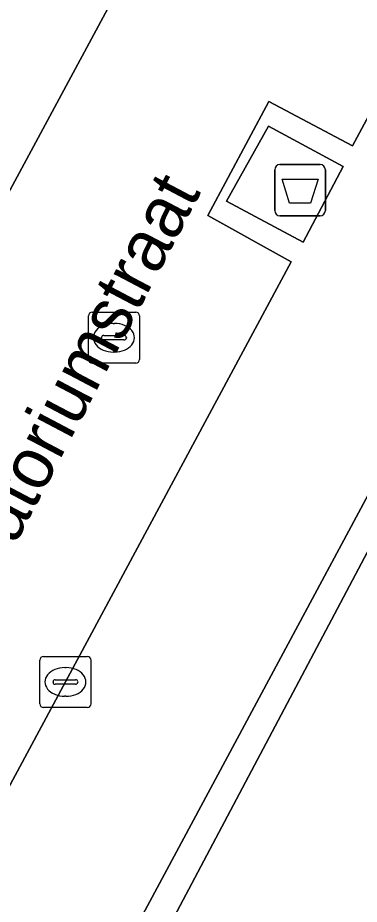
# Model space of a CAD drawing. Extents: x 159489 to 160304, y 383825 to 384531.
# Drawn here: x 159635.59 to 159642.27, y 384190.24 to 384207.56 of the extents above; entities that cross this region are included whole.
import ezdxf

# ---------------------------------------------------------------- set-up
doc = ezdxf.new("R2010")
doc.units = 0
for name, color, linetype in [('IMGEO_Afval_apart_plaats', 7, 'Continuous'), ('IMGEO_Groenvoorziening', 7, 'Continuous'), ('IMGEO_Haag', 7, 'Continuous'), ('IMGEO_Kolk', 7, 'Continuous'), ('IMGEO_Openbare_ruimte_label', 7, 'Continuous'), ('IMGEO_Parkeervlak_open', 7, 'Continuous'), ('IMGEO_Rijbaan_lokaal_gesloten', 7, 'Continuous'), ('IMGEO_Rioolput', 7, 'Continuous'), ('IMGEO_Voetpad_gesloten', 7, 'Continuous'), ('IMGEO_Voetpad_open', 7, 'Continuous')]:
    doc.layers.add(name, color=color, linetype=linetype)

msp = doc.modelspace()

# ---------------------------------------------------------------- linework, layer by layer
at = {"layer": 'IMGEO_Afval_apart_plaats'}
for p, q in [((159640.715, 384204.69), (159641.505, 384204.69)), ((159641.505, 384204.69), (159640.715, 384204.69)), ((159640.615, 384203.79), (159640.615, 384204.59)), ((159640.615, 384204.59), (159640.615, 384203.79)), ((159641.605, 384204.59), (159641.605, 384203.79)), ((159641.605, 384203.79), (159641.605, 384204.59)), ((159641.505, 384203.69), (159640.715, 384203.69)), ((159640.715, 384203.69), (159641.505, 384203.69))]:
    msp.add_line(p, q, dxfattribs=at)
msp.add_lwpolyline([(159640.758, 384204.404), (159641.462, 384204.404), (159641.313, 384203.934), (159640.907, 384203.934), (159640.758, 384204.404)], dxfattribs=at)
for centre, start, end in [((159640.715, 384204.59), 90, 180), ((159640.715, 384204.59), 90, 180), ((159641.505, 384204.59), 0, 90), ((159641.505, 384204.59), 360, 90), ((159640.715, 384203.79), 180, 270), ((159640.715, 384203.79), 180, 270), ((159641.505, 384203.79), 270, 0), ((159641.505, 384203.79), 270, 0)]:
    msp.add_arc(centre, 0.1, start, end, dxfattribs=at)
at = {"layer": 'IMGEO_Groenvoorziening'}
for points in [[(159638.312, 384209.524), (159639.366, 384211.481), (159637.113, 384212.661), (159633.141, 384205.225), (159635.354, 384204.03)], [(159637.45, 384187.678), (159638.592, 384189.885), (159647.537, 384206.76), (159652.006, 384204.401), (159652.186, 384204.749), (159647.326, 384207.335), (159624.039, 384163.992), (159628.847, 384161.508), (159629.249, 384161.301), (159629.469, 384161.725), (159624.879, 384164.058), (159626.156, 384166.276)]]:
    msp.add_lwpolyline(points, close=True, dxfattribs=at)
at = {"layer": 'IMGEO_Haag'}
msp.add_lwpolyline([(159637.45, 384187.678), (159638.592, 384189.885), (159647.537, 384206.76), (159652.006, 384204.401), (159652.186, 384204.749), (159647.326, 384207.335), (159624.039, 384163.992), (159628.847, 384161.508), (159629.249, 384161.301), (159629.469, 384161.725), (159624.879, 384164.058), (159626.156, 384166.276)], close=True, dxfattribs=at)
at = {"layer": 'IMGEO_Kolk'}
for p, q in [((159636.024, 384194.157), (159636.024, 384195.009)), ((159636.099, 384195.083), (159636.951, 384195.083)), ((159637.025, 384195.009), (159637.025, 384194.157)), ((159636.512, 384194.863), (159636.537, 384194.863)), ((159636.326, 384194.626), (159636.724, 384194.626)), ((159636.283, 384194.577), (159636.283, 384194.589)), ((159636.721, 384194.54), (159636.323, 384194.54)), ((159636.767, 384194.589), (159636.767, 384194.577)), ((159636.535, 384194.303), (159636.51, 384194.303)), ((159636.951, 384194.083), (159636.099, 384194.083))]:
    msp.add_line(p, q, dxfattribs=at)
for points in [[(159636.024, 384194.157), (159636.024, 384195.009)], [(159636.099, 384195.083), (159636.951, 384195.083)], [(159637.025, 384195.009), (159637.025, 384194.157)], [(159636.951, 384194.083), (159636.099, 384194.083)]]:
    msp.add_lwpolyline(points, dxfattribs=at)
for centre, radius, start, end in [((159636.101, 384195.007), 0.0765, 91.552, 178.448), ((159636.101, 384195.007), 0.0765, 91.552, 178.448), ((159636.949, 384195.007), 0.0765, 1.552, 88.448), ((159636.949, 384195.007), 0.0765, 1.552, 88.448), ((159636.323, 384194.586), 0.0403, 85.8775, 175.7526), ((159636.728, 384194.588), 0.0386, 1.7309, 96.639), ((159636.32, 384194.576), 0.0366, 178.938, 274.7102), ((159636.724, 384194.583), 0.043, 264.8664, 352.4533), ((159636.101, 384194.159), 0.0765, 181.552, 268.448), ((159636.101, 384194.159), 0.0765, 181.552, 268.448), ((159636.949, 384194.159), 0.0765, 271.552, 358.448), ((159636.949, 384194.159), 0.0765, 271.552, 358.448)]:
    msp.add_arc(centre, radius, start, end, dxfattribs=at)
for centre, major_axis, ratio, start_param, end_param in [((159636.511, 384194.583), (-0.387, 0.002), 0.722429, 4.712389, 7.853982), ((159636.536, 384194.583), (-0.39, 0.002), 0.717154, 1.570796, 4.712389)]:
    msp.add_ellipse(centre, major_axis=major_axis, ratio=ratio, start_param=start_param, end_param=end_param, dxfattribs=at)
at = {"layer": 'IMGEO_Parkeervlak_open'}
msp.add_lwpolyline([(159652.006, 384204.401), (159647.537, 384206.76), (159638.592, 384189.885), (159643.082, 384187.51)], close=True, dxfattribs=at)
at = {"layer": 'IMGEO_Rijbaan_lokaal_gesloten'}
for points in [[(159654.684, 384240.484), (159653.747, 384238.682), (159646.166, 384224.11), (159643.655, 384219.446), (159639.366, 384211.481), (159638.312, 384209.524), (159635.354, 384204.03), (159631.805, 384197.437), (159631.422, 384196.726), (159624.053, 384183.005), (159617.514, 384170.805), (159617.293, 384170.392), (159616.523, 384168.93), (159615.471, 384167.017)], [(159636.525, 384194.583), (159640.934, 384202.788), (159639.307, 384203.695), (159640.5, 384205.922), (159642.138, 384205.059), (159643.404, 384207.416), (159644.131, 384208.747), (159647.908, 384215.784), (159651.321, 384222.115), (159658.978, 384236.342), (159659.656, 384237.603), (159660.392, 384238.832)], [(159617.96, 384161.026), (159619.063, 384162.111), (159619.143, 384162.254), (159621.259, 384166.179), (159621.791, 384167.209), (159629.16, 384180.893), (159636.525, 384194.583)]]:
    msp.add_lwpolyline(points, dxfattribs=at)
at = {"layer": 'IMGEO_Rioolput'}
for p, q in [((159636.973, 384200.882), (159636.973, 384201.734)), ((159637.048, 384201.808), (159637.9, 384201.808)), ((159637.974, 384201.734), (159637.974, 384200.882)), ((159637.461, 384201.588), (159637.486, 384201.588)), ((159637.232, 384201.302), (159637.232, 384201.314)), ((159637.67, 384201.265), (159637.272, 384201.265)), ((159637.275, 384201.351), (159637.673, 384201.351)), ((159637.716, 384201.314), (159637.716, 384201.302)), ((159637.484, 384201.028), (159637.459, 384201.028)), ((159637.9, 384200.808), (159637.048, 384200.808))]:
    msp.add_line(p, q, dxfattribs=at)
for points in [[(159636.973, 384200.882), (159636.973, 384201.734)], [(159637.048, 384201.808), (159637.9, 384201.808)], [(159637.974, 384201.734), (159637.974, 384200.882)], [(159637.9, 384200.808), (159637.048, 384200.808)]]:
    msp.add_lwpolyline(points, dxfattribs=at)
for centre, radius, start, end in [((159637.05, 384201.732), 0.0765, 91.552, 178.448), ((159637.05, 384201.732), 0.0765, 91.552, 178.448), ((159637.898, 384201.732), 0.0765, 1.552, 88.448), ((159637.898, 384201.732), 0.0765, 1.552, 88.448), ((159637.272, 384201.311), 0.0403, 85.8775, 175.7526), ((159637.269, 384201.301), 0.0366, 178.938, 274.7102), ((159637.673, 384201.308), 0.043, 264.8664, 352.4533), ((159637.677, 384201.313), 0.0386, 1.7309, 96.639), ((159637.05, 384200.884), 0.0765, 181.552, 268.448), ((159637.05, 384200.884), 0.0765, 181.552, 268.448), ((159637.898, 384200.884), 0.0765, 271.552, 358.448), ((159637.898, 384200.884), 0.0765, 271.552, 358.448)]:
    msp.add_arc(centre, radius, start, end, dxfattribs=at)
for centre, major_axis, ratio, start_param, end_param in [((159637.46, 384201.308), (-0.387, 0.002), 0.722429, 4.712389, 7.853982), ((159637.485, 384201.308), (-0.39, 0.002), 0.717154, 1.570796, 4.712389)]:
    msp.add_ellipse(centre, major_axis=major_axis, ratio=ratio, start_param=start_param, end_param=end_param, dxfattribs=at)
at = {"layer": 'IMGEO_Voetpad_gesloten'}
msp.add_lwpolyline([(159641.952, 384204.655), (159640.492, 384205.437), (159639.672, 384203.978), (159641.17, 384203.172)], close=True, dxfattribs=at)
at = {"layer": 'IMGEO_Voetpad_open'}
for points in [[(159647.326, 384207.335), (159649.078, 384210.598), (159649.663, 384210.272), (159651.431, 384213.623), (159651.297, 384213.694), (159651.4, 384213.888), (159648.7, 384215.354), (159644.915, 384208.328), (159644.131, 384208.747), (159643.404, 384207.416), (159642.138, 384205.059), (159640.5, 384205.922), (159639.307, 384203.695), (159640.934, 384202.788), (159636.525, 384194.583), (159629.16, 384180.893), (159621.791, 384167.209), (159621.259, 384166.179), (159622.029, 384165.74), (159619.927, 384161.842), (159619.143, 384162.254), (159619.063, 384162.111), (159617.96, 384161.026)], [(159613.734, 384158.126), (159604.421, 384153.122), (159601.595, 384151.633), (159604.764, 384149.496), (159618.169, 384156.621), (159620.642, 384157.928), (159622.146, 384160.474), (159622.471, 384161.072), (159624.039, 384163.992), (159647.326, 384207.335)]]:
    msp.add_lwpolyline(points, dxfattribs=at)
msp.add_lwpolyline([(159639.672, 384203.978), (159640.492, 384205.437), (159641.952, 384204.655), (159641.17, 384203.172)], close=True, dxfattribs=at)

# ---------------------------------------------------------------- texts
at = {"layer": 'IMGEO_Openbare_ruimte_label'}
msp.add_text('Laboratoriumstraat', height=1, rotation=62.2041, dxfattribs=at).set_placement((159633.945, 384194.224))

doc.saveas('drawing.dxf')
